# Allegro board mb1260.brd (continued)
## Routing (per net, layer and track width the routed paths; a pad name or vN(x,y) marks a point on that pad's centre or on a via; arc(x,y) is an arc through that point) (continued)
LCD_PSRAM_D12: length 52.1
  TOP w0.127: U10.E2 v2(45.2,32.89) ; U8.R11 37.76,41.46 v2(37.63,41.33)
  L4_SIG w0.102: v2(45.2,32.89) 45.69,32.89 45.82,33.02 45.82,33.43 45.95,33.55 46.18,33.55 46.3,33.43 46.3,32.56 46.18,32.44 45.19,32.44 45.06,32.31 45.06,32.13 45.19,32 45.52,32 45.64,31.88 45.64,31.65 45.52,31.52 44.63,31.52 43.92,30.81 43.92,27.61 44.3,27.23 44.3,24.82 44.17,24.69 43.28,24.69 43.15,24.56 43.15,24.36 43.28,24.23 44.22,24.23 44.35,24.1 44.35,23.9 44.22,23.77 43.28,23.77 43.15,23.65 43.15,18.26 43.79,17.63 44.7,17.63 44.83,17.5 44.83,17.25 44.7,17.12 44.22,17.12 44.09,16.99 44.09,16.76 44.22,16.64 v1(44.42,16.64)
  BOTTOM w0.127: v2(37.63,41.33) 37.63,41.71 37.75,41.83 38.05,41.83 38.18,41.71 38.18,41.12 38.3,41 38.56,41 38.68,41.12 38.68,42.08 38.56,42.2 37.26,42.2 37.13,42.08 37.13,41.15 37.26,41.02 37.26,39.49 37.95,38.81 38.69,38.81 39.32,38.18 40.16,38.18 40.82,37.52 41.69,37.52 42.04,37.17 42.04,36.7 43.31,35.43 43.31,34.29 43.84,33.76 44.04,33.76 44.4,33.4 45.8,33.4 45.95,33.25 45.95,32.38 45.82,32.26 45.57,32.26 45.44,32.38 45.44,32.76 45.31,32.89 v2(45.2,32.89) ; v1(44.42,16.64) 44.42,16.36 43.23,15.16 CN17.6
LCD_PSRAM_D13: length 46.7
  TOP w0.127: v2(41.4,41.68) 41.4,41.73 41.53,41.86 41.87,41.86 42,41.73 42,40.74 42.13,40.61 42.38,40.61 42.48,40.71 42.48,42.06 42.38,42.16 40.91,42.16 40.58,42.49 40.45,42.49 U8.P15 ; U10.F2 44.6,32.49 44.48,32.62 44.48,33.78 44.35,33.91 44.09,33.91 43.97,34.04 43.97,36.53 44.07,36.63 44.37,36.63 44.5,36.5 44.5,35.51 44.63,35.38 v2(45.24,35.38)
  L4_SIG w0.102: v1(42.93,16.74) 42.93,16.97 42.21,17.68 42.21,26.11 42.27,26.16 42.27,29.62 42.39,29.74 42.95,29.74 43.08,29.87 43.08,31.39 44.07,32.38 44.07,33.17 45.67,34.77 45.67,35.18 45.47,35.38 v2(45.24,35.38)
  BOTTOM w0.127: v2(45.24,35.38) 45.29,35.38 45.8,34.87 46.2,34.87 46.96,35.64 46.96,36.51 46.19,37.29 45.16,37.29 45.16,37.29 45.15,37.29 44.89,37.55 44.89,37.56 44.88,37.57 44.88,38.6 43.54,39.94 42.86,39.94 42.09,40.72 42.09,41.12 41.91,41.51 41.73,41.68 v2(41.4,41.68) ; CN17.5 v1(42.93,16.74)
LCD_PSRAM_D14: length 47.8
  TOP w0.127: U8.P14 39.39,42.26 v2(39.39,42.25) ; v2(45.21,34.85) 44.45,34.85 44.35,34.75 44.35,34.54 44.48,34.42 45.34,34.42 45.47,34.29 45.47,34.04 45.34,33.91 44.98,33.91 44.85,33.78 U10.F1
  L4_SIG w0.102: v2(45.21,34.85) 45.09,34.85 43.21,32.97 43.21,32.31 42.57,31.67 42.57,30.61 41.94,29.97 41.94,26.95 41.48,26.49 41.48,18.19 41.58,18.08 41.74,18.08 41.87,17.96 41.87,17.81 41.74,17.68 41.58,17.68 41.48,17.58 41.48,17.35 41.61,17.22 42.11,17.22 42.24,17.09 42.24,16 42.14,15.9 42.14,14.25 v1(42.57,13.82)
  BOTTOM w0.127: v2(45.21,34.85) 45.16,34.8 44.96,34.8 44.83,34.92 44.83,35.94 44.96,36.07 45.9,36.07 46.02,36.2 46.02,36.38 45.88,36.53 44.85,36.53 44.84,36.53 44.83,36.53 44.53,36.83 44.06,36.83 43.56,37.33 43.56,38.84 43.22,39.18 42.25,39.18 42.12,39.04 41.45,39.04 41.33,39.17 41.33,39.84 40.64,40.53 40.64,42.14 40.84,42.34 40.84,42.6 40.84,42.6 40.63,42.81 40.63,43.07 40.51,43.18 39.27,43.18 39.14,43.05 39.14,42.87 39.27,42.75 40.16,42.75 40.31,42.6 40.31,42.29 40.08,42.06 39.57,42.06 39.39,42.24 v2(39.39,42.25) ; CN17.4 42.63,13.87 v1(42.57,13.82)
LCD_PSRAM_D15: length 47.9
  TOP w0.127: v2(45.85,35.66) 45.9,35.71 45.9,36.88 45.77,37.01 45.52,37.01 45.39,36.88 45.39,36.04 45.26,35.92 45.06,35.92 44.93,36.04 44.93,36.98 44.81,37.11 43.71,37.11 43.59,36.98 43.59,33.76 U10.G1 ; v2(41,42.96) 41,42.97 40.94,43.03 40.69,43.03 40.49,43.23 U8.N15
  L4_SIG w0.102: v2(45.85,35.66) 45.75,35.76 45.08,35.76 44.86,35.54 44.86,35.53 44.7,35.38 43.59,34.14 43.17,33.68 42.55,32.62 41.99,31.69 41.68,30.65 41.17,26.67 41.17,16.66 41.38,16.23 v1(41.71,15.9)
  BOTTOM w0.127: v2(45.85,35.66) 45.85,35.46 45.95,35.36 46.15,35.36 46.58,35.79 46.58,36.36 46.03,36.91 45,36.91 45,36.91 44.99,36.91 44.69,37.21 44.22,37.21 43.94,37.49 43.94,38.05 44.07,38.18 44.32,38.18 44.45,38.3 44.45,38.49 44.31,38.63 44.09,38.63 43.94,38.79 43.94,39 43.38,39.56 43.02,39.56 42.58,39.56 42.45,39.69 42.45,39.81 42.16,40.11 41.81,40.11 41.71,40.21 41.71,41.04 41.68,41.1 41.49,41.29 41.19,41.29 41,41.48 41,42.04 41.12,42.16 41.33,42.16 41.44,42.28 41.44,42.49 41.26,42.88 41.17,42.96 v2(41,42.96) ; CN17.3 42.33,16.53 41.71,15.91 v1(41.71,15.9)
LCD_PSRAM_NOE: length 56.7
  TOP w0.127: v2(36.75,48.69) 36.75,48.72 U8.D10 ; U10.A2 48.6,32.55 v2(49.94,33.88)
  L4_SIG w0.102: v1(51.69,18.03) 51.79,18.14 51.79,18.77 51.82,18.8 51.82,18.8 52.07,19.05 52.07,19.05 52.2,19.18 52.2,31.22 49.94,33.48 v2(49.94,33.88) 49.94,33.93 50.06,34.06 51.18,34.06 51.31,34.19 51.31,35.48 50.06,36.73 47.9,36.73 47.42,37.21 46.57,37.21 46.47,37.31 46.47,37.42 46.35,37.54 46.18,37.54 46.06,37.42 46.06,37.31 45.96,37.21 43.93,37.21 43.83,37.31 43.83,37.7 43.71,37.82 43.54,37.82 43.42,37.7 43.42,37.31 43.32,37.21 41.5,37.21 41.39,37.33 41.39,38.7 41.35,38.74 41.35,38.74 40.61,39.49 40.61,40.82 40.03,41.4 38.86,41.4 37.85,42.42 36.77,42.42 36.4,42.79 36.4,48.33 36.75,48.69 v2(36.75,48.69)
  BOTTOM w0.127: v1(51.69,18.03) 51.94,17.78 51.94,16.84 50.83,15.72 48.67,15.72 47.13,17.26 CN17.19
LCD_PSRAM_NWE: length 57.3
  TOP w0.127: v1(52.02,40.39) 52.58,40.39 52.88,40.08 52.88,23.24 51.99,22.35 48.9,22.35 R64.1 44.07,21.36 45.97,19.46 45.97,17.78 46.86,16.89 v1(46.86,16.76) ; v2(37.44,50.06) U8.C11
  L4_SIG w0.102: v1(52.02,40.39) 52.02,40.56 49.43,43.15 47.96,43.15 45.42,45.69 40.41,45.69 39.64,46.47 39.09,46.79 38.07,47.8 38.07,49.05 37.66,49.83 v2(37.44,50.06)
  BOTTOM w0.127: v1(46.86,16.76) 47,16.76 47.37,16.38 47.37,14.68 CN17.20
LCD_RST: length 43
  TOP w0.127: v1(52.25,18.62) 52.12,18.49 51.51,18.49 51.18,18.16 51.18,17.4 ; U8.N12 v2(38.74,42.91)
  L4_SIG w0.102: v1(52.25,18.62) 52.5,18.87 52.5,31.75 51.94,32.31 51.94,35.31 50.19,37.06 48.11,37.06 46.48,38.68 44.75,38.68 42.57,40.86 42.57,41.42 41.85,42.15 41.31,42.15 41.28,42.12 40.31,42.12 39.61,42.82 38.82,42.82 v2(38.74,42.91)
  BOTTOM w0.127: CN17.23 48.33,16.82 49.05,16.1 50.6,16.1 51.22,16.73 51.22,18.2 51.51,18.49 52.12,18.49 v1(52.25,18.62)
LCD_TE_INT: length 64
  TOP w0.127: v2(42.19,46.51) 42.06,46.51 41.69,46.88 41.6,46.88 40.97,47.5 40.53,47.5 40.48,47.45 40.03,47.45 U8.G14
  L4_SIG w0.102: v1(56.52,41.02) 56.77,40.77 56.77,34.67 57.4,34.04 57.4,23.88 58.04,23.24 58.04,15.75 v1(57.4,15.11)
  BOTTOM w0.127: v1(56.52,41.02) 51.51,46.02 48.47,46.02 47.7,46.02 47.62,46.1 42.6,46.1 v2(42.19,46.51) ; v1(57.4,15.11) 52.96,15.11 51.82,13.97 50.9,13.97 49.88,12.95 47.99,12.95 47.57,13.37 42.31,13.37 42.03,13.65 CN17.2
LED_STLINK: length 22.6
  TOP w0.127: v1(47.37,76.52) 47.43,76.59 U2.30 ; v1(38.1,82.04) R14.1 R13.1
  L4_SIG w0.102: v1(38.1,82.04) 38.1,81.92 41.91,78.11 43.56,78.11 44.7,76.96 46.93,76.96 v1(47.37,76.52)
LEDA: length 26.5
  TOP w0.127: L8.2 v1(28.83,11.81)
  L4_SIG w0.102: v1(50.8,14.73) 50.8,13.72 50.04,12.95 48.13,12.95 46.48,11.3 39.22,11.3 38.18,12.34 29.36,12.34 v1(28.83,11.81)
  BOTTOM w0.127: v1(50.8,14.73) 50.7,14.63 CN17.28
LEDK: length 34.4
  TOP w0.127: v1(22.34,22.73) 22.34,22.72 R66.2 21.91,21.65 U12.4
  BOTTOM w0.127: v1(22.34,22.73) 22.35,22.73 23.11,21.97 24.64,21.97 26.54,20.07 35.48,20.07 36.36,19.19 50.53,19.19 50.75,18.97 50.75,18.36 50.13,17.74 CN17.29
MIC_VDD1: length 9.4
  TOP w0.127: 7.49,64.59 7.49,64.81
  TOP w0.229: 13,60.44 U7.A7
  TOP w0.508: 7.49,64.59 TP1.1 8.76,62.36 C29.2 12.4,60.58 12.54,60.44 13,60.44
MIC_VDD2: length 7.9
  TOP w0.127: TP2.1 7.62,59.94 9.78,59.94 C31.2 10.77,59.18 v1(11.48,59.89) ; 14.12,59.94 U7.B6 14.12,59.94 ; 14.12,59.94 v3(13.96,59.78)
  BOTTOM w0.127: v3(13.96,59.78) 13.96,59.63 13.59,59.26 13.31,59.26 12.95,59.61 11.76,59.61 v1(11.48,59.89)
NC1: length 8.2
  TOP w0.127: U8.B5 33.53,50.71 33.53,51.64 33.55,51.66 33.55,52.28 33.17,52.65 32.69,52.65 32.41,52.94 32.41,53.42 32.7,53.71 32.7,55.96 32.64,56.03 32.64,56.64 TP3.1
NC4: length 4.4
  TOP w0.102: 36.78,52.17 36.78,50.7 U8.B9
  TOP w0.127: TP5.1 37.08,53.1 36.78,52.8 36.78,52.17
NC8: length 8.5
  TOP w0.127: U8.D2 31.6,49.4 30.93,49.4 30.81,49.52 30.47,49.52 30.24,49.75 30.24,50.12 29.43,50.93 26.04,50.93 TP14.1
NC10: length 13.6
  TOP w0.127: v1(25.7,53.52) 25.65,53.57 25.65,54.86 26.54,55.75 TP8.1 ; v2(33.55,48.75) 33.53,48.75 U8.E4
  BOTTOM w0.127: v2(33.55,48.75) 33.03,48.75 32.29,49.49 32.29,49.95 31.27,50.98 30.07,50.98 29.14,51.91 27.62,51.91 26.06,53.47 25.76,53.47 v1(25.7,53.52)
NC11: length 9.6
  TOP w0.127: TP13.1 23.75,52.07 24.51,51.31 25.12,51.31 25.88,50.55 29.21,50.55 29.86,49.9 29.86,49.52 30.29,49.08 U8.D1
NETB1_2: length 7.6
  BOTTOM w0.127: B1.2 B1.4 77.84,43.07 77.85,43.05 76.58,43.05
NETB2_1: length 7.9
  BOTTOM w0.127: B2.1 73.82,33.86 SB34.2 73.84,34.8 R91.1 C87.2 77.85,33.05 B2.3
NETC8_2: length 1.7
  TOP w0.508: U3.4 59.88,74.48 C8.2
NETC9_2: length 7.1
  TOP w0.508: 65.91,72.9 65.59,72.9 65.28,72.58 U3.1 ; 65.91,72.9 65.91,71.25 ; 65.91,72.9 65.91,74.17 C9.2 65.6,74.48 U3.3
NETC18_1: length 6.3
  TOP w0.127: U7.B7 v3(13.96,60.6)
  TOP w0.381: v1(12.06,62.1) 12.06,62.84 10.67,64.24 C18.1
  BOTTOM w0.254: v3(13.96,60.6) 13.94,60.58 12.57,60.58 12.06,61.09 v1(12.06,62.1)
NETC18_2: length 28.1
  TOP w0.381: C18.2 10.67,68.16 18.16,75.65 18.16,84.07 19.32,85.23 CN4.4
NETC19_2: length 4.8
  TOP w0.127: C19.2 12.06,63.63 12.95,62.74 14.1,62.74 14.62,62.22 U7.C9
NETC21_1: length 3.2
  TOP w0.127: U7.D9 15.12,64.13 C21.1
NETC24_1: length 5.9
  TOP w0.127: v1(18.16,63.75) 18.16,63.88 C24.1 ; U7.E6 v3(15.78,60.1)
  BOTTOM w0.127: v1(18.16,63.75) 16.33,61.93 16.33,60.65 v3(15.78,60.1)
NETC25_1: length 5
  TOP w0.127: U7.H8 17.25,60.94 18.54,62.23 18.54,62.74 C25.1
NETC25_2: length 6.6
  TOP w0.127: v1(19.66,65.3) 19.66,65.38 C25.2 ; U7.G8 v3(16.78,61.1)
  BOTTOM w0.127: v3(16.78,61.1) 16.87,61.19 16.87,61.77 19.66,64.57 v1(19.66,65.3)
NETC26_1: length 4.7
  TOP w0.127: C26.1 19.68,63.12 v1(19.3,62.74) ; U7.G7 v3(16.78,60.6)
  BOTTOM w0.127: v3(16.78,60.6) 16.87,60.69 17.25,60.69 v1(19.3,62.74)
NETC27_1: length 8
  TOP w0.127: U7.D7 v3(14.96,60.6)
  TOP w0.381: C27.1 10.79,62.97 10.79,62.36 11.86,61.29 12.75,61.29 v1(12.95,61.09)
  BOTTOM w0.254: v3(14.96,60.6) 14.71,60.6 14.1,61.21 13.08,61.21 v1(12.95,61.09)
NETC27_2: length 18.2
  TOP w0.381: CN4.6 11.32,70.68 9.02,68.38 9.02,66.27 C27.2
NETC28_1: length 3.6
  TOP w0.127: C28.1 18.54,61.59 17.38,60.44 U7.H7
NETC30_1: length 29.2
  TOP w0.127: U7.H6 17.65,59.94
  TOP w0.381: 17.65,59.94 17.91,60.2 C30.1 20.07,60.45 20.45,60.83 22.35,60.83 24.89,63.37 24.89,82.91 CN5.6
NETC30_2: length 1.1
  TOP w0.127: C30.2 R31.1
NETC32_1: length 44.9
  TOP w0.127: U7.G6 v3(16.78,60.1)
  TOP w0.381: v1(18.49,59.61) 18.92,59.18 C32.1 20.83,58.42 24,58.42 24.77,59.18 24.77,61.85 25.78,62.87 25.78,77.47 27.81,79.5 27.81,80.7 29.34,82.22 30.76,82.22 33.14,84.6 CN5.4
  BOTTOM w0.381: v1(18.49,59.61) 18.01,60.1 v3(16.78,60.1)
NETC32_2: length 1.1
  TOP w0.127: C32.2 R33.1
NETC43_2: length 3.6
  TOP w0.127: C43.2 16.12,55.59 U7.F1
NETC48_2: length 4.9
  TOP w0.152: R49.1 26.67,48.39 25.4,48.39 C48.2 23.63,49.02 X2.1
NETC51_2: length 4.7
  TOP w0.152: R50.1 26.67,47.88 24.89,47.88 C51.2 24.51,48.26 23.38,48.26 X2.2
NETC67_1: length 8.2
  TOP w0.508: C67.1 L2.2 L3.2 L4.1 24.51,27.05 C69.2
NETC75_2: length 15.9
  TOP w0.381: U12.6 22.56,16.46
  TOP w0.508: C75.2 21.26,13.16 ; C75.2 21.26,11.23 ; C75.2 20.47,12.19 ; C75.2 22.05,12.19 ; 22.35,9.68 C76.2 ; C76.2 21.7,10.29 ; C76.2 22.35,10.9 ; 22.25,13.65 Z1.2 ; Z1.2 22.25,16.32 ; Z1.2 20.9,14.99 ; L8.1 26.42,10.41 25.4,9.4 22.73,9.4
NETC86_2: length 2.8
  BOTTOM w0.127: R90.1 C86.2 73.84,42.04 SB33.2
NETCN7_1: length 14.5
  TOP w0.127: U7.C3 v3(14.46,58.6)
  BOTTOM w0.203: 12.56,58.27 12.62,58.27 12.63,58.25 12.69,58.25 12.85,58.09 13.77,58.09 13.86,58.18 14.19,58.18 14.46,58.45 v3(14.46,58.6)
  BOTTOM w0.508: CN7.1 4.38,59.56 4.01,59.94 4.01,60.59 4.55,61.13 5.75,61.13 7.52,59.36 8.64,59.36 9.73,58.27 12.56,58.27
NETCN7_2: length 14.5
  TOP w0.127: U7.B3 v3(13.96,58.6)
  BOTTOM w0.203: 12.73,58.86 13.17,58.42 13.65,58.42 13.83,58.6 v3(13.96,58.6)
  BOTTOM w0.508: CN7.2 2.77,59.56 3.25,60.05 3.25,60.9 4.23,61.89 6.06,61.89 7.83,60.12 8.95,60.12 10.04,59.03 12.56,59.03 12.73,58.86
NETCN10_1: length 13.3
  TOP w0.203: v3(13.65,56.74) 14.07,57.16 14.07,57.39 U7.B1
  BOTTOM w0.508: v3(13.65,56.74) 13.27,56.74 12.51,55.98 7.59,55.98 6.63,56.95 4.5,56.95 4.06,56.51 4.06,55.85 4.42,55.5 CN10.1
NETCN10_2: length 13.3
  TOP w0.203: U7.A2 13.38,57.94 v3(12.91,57.46)
  BOTTOM w0.508: v3(12.91,57.46) 12.91,57.46 12.19,56.74 7.91,56.74 6.94,57.71 4.19,57.71 3.3,56.82 3.3,55.88 2.92,55.5 CN10.2
NETCN11_8: length 2.4
  TOP w0.508: 61.34,44.83 61.37,44.8 CN11.8
NETCN12_1: length 2.8
  TOP w0.508: R58.1 15.52,40.77 CN12.1
NETCN14_1: length 10.8
  BOTTOM w0.127: R92.2 6.68,24.77 6.15,24.23 5.36,24.23 5.05,23.93 5.05,22.83 5.69,22.2 9.5,22.2 CN14.1
NETCN14_8: length 18.2
  BOTTOM w0.127: CN14.8 3.38,22.68 4.78,21.29 4.78,20.04 5.33,19.48 11.94,19.48 12.27,19.81 12.27,23.9 R97.1
NETCN15_5: length 4.2
  BOTTOM w0.127: CN15.5 15.5,7.73 SB36.2 19.72,7.73
NETCN15_6: length 5
  BOTTOM w0.127: CN15.6 16.38,5.18 17.52,4.04 SB38.2 SB37.2
NETCN16_8: length 8.5
  BOTTOM w0.127: CN16.8 25.7,79.96 26.29,79.38 26.29,77.85 25.42,76.98 25.42,75.79 24.66,75.03 ; 24.66,75.03 SB2.1 ; 24.66,75.03 SB4.1
NETCN17_24: length 4.2
  TOP w0.127: v1(48.53,13.45) 48.11,13.86 SB16.2 SB15.2
  BOTTOM w0.127: CN17.24 48.63,13.55 v1(48.53,13.45)
NETD1_2: length 8.3
  TOP w0.127: D1.2 45.97,91.71 45.97,83.95
NETD2_2: length 39.3
  TOP w0.508: 67.12,71.26 67.84,71.26 68.3,70.79 68.3,42.75 67.3,41.75 D5.2 D4.2 D3.2 D2.2
NETL6_2: length 6.7
  TOP w0.254: U12.8 24.13,17.18 24.13,15.39 Z1.1
  TOP w0.508: L6.2 25.91,17.45 25.15,16.69 25.15,15.6 Z1.1
NETL7_2: length 7.2
  TOP w0.254: v1(25.91,16.26) 26.29,16.26 R69.2 R71.2 26.67,13.46 L7.2 ; v1(23.62,16.51) 23.21,16.92 U12.7
  L4_SIG w0.254: v1(25.91,16.26) 25.65,16.51 v1(23.62,16.51)
NETLD1_1: length 1.8
  BOTTOM w0.127: LD1.1 R12.1
NETLD2_1: length 1.5
  TOP w0.127: LD2.1 41.27,92.58 R1.2
NETLD3_1: length 1.4
  TOP w0.127: LD3.1 R2.1
NETLD3_2: length 18.6
  TOP w0.127: LD3.2 58.93,93.87 v1(58.78,93.87)
  TOP w0.508: U1.8 62.1,80.01 v1(61.47,80.64) R15.1
  BOTTOM w0.127: v1(58.78,93.87) 58.8,93.84 58.8,83.31 v1(61.47,80.64)
NETLD4_2: length 1.8
  TOP w0.127: LD4.2 38.09,89.93 R14.2
NETLD4_3: length 1.8
  TOP w0.127: R13.2 36.59,89.93 LD4.3
NETLD5_1: length 1.5
  BOTTOM w0.127: LD5.1 R47.2
NETLD6_1: length 1.5
  BOTTOM w0.127: LD6.1 R48.2
NETLD7_1: length 1.8
  TOP w0.127: v1(38.76,2.29) R81.2
  BOTTOM w0.127: v1(38.76,2.29) R81.2
NETLD7_2: length 13.1
  TOP w0.127: v1(37.85,4.67) 40.77,7.59 40.77,9.78 R78.1 38.73,10.92 38.03,10.22 U13.3 38.09,9.4 R80.2
  BOTTOM w0.127: LD7.2 v1(37.85,4.67)
NETLD8_1: length 2
  TOP w0.127: R82.1 v1(40.77,2.29)
  BOTTOM w0.127: R82.1 v1(40.77,2.29)
NETLD8_2: length 7.6
  TOP w0.127: T1.3 44.03,8.92 v1(39.75,4.65)
  BOTTOM w0.127: LD8.2 v1(39.75,4.65)
NETLD9_1: length 1.8
  TOP w0.127: v1(58.17,2.29) R83.1
  BOTTOM w0.127: R83.1 v1(58.17,2.29)
NETLD9_2: length 16.4
  TOP w0.127: T2.3 47.96,7.03 48.39,6.6 58.5,6.6 59.05,6.05 v1(59.05,4.67)
  BOTTOM w0.127: LD9.2 v1(59.05,4.67)
NETLD10_1: length 1.8
  TOP w0.127: R84.1 v1(60.07,2.29)
  BOTTOM w0.127: R84.1 v1(60.07,2.29)
NETR3_2: length 1.8
  TOP w0.127: U2.44 44.84,82.92 R3.2
NETR7_1: length 4.3
  TOP w0.127: 51.69,83.95 v1(50.93,83.95) 49.02,83.95
  BOTTOM w0.127: v1(50.93,83.95) 50.67,83.95 49.85,83.12 T3.1
NETR10_1: length 3.2
  TOP w0.155: R10.1 v1(50.87,84.96)
  BOTTOM w0.155: v1(50.87,84.96) 51.75,84.08 T3.2
NETR12_2: length 126.2
  TOP w0.127: v1(61.34,41.66) 61.34,40.77
  L4_SIG w0.102: v1(61.34,41.66) 60.83,42.16 54.81,42.16 51.94,45.03 51.94,70.48 53.34,71.88 53.34,74.04 52.45,74.93 45.47,74.93 43.03,77.37 41.63,77.37 38,81 22.53,81 20.09,78.56 20.09,77.58 22.56,75.12 24.2,75.12 24.89,74.42 24.89,61.09 24,60.2 24,55.63 18.03,49.66 13.97,49.66 v1(10.67,46.35)
  BOTTOM w0.127: R12.2 9.91,47.12 v1(10.67,46.35)
NETR17_2: length 2.7
  TOP w0.127: U2.2 40.37,79.08 40.01,79.45 40.01,79.88 R17.2
NETR19_2: length 2.3
  TOP w0.127: U2.3 40.29,78.59 R19.2
NETR22_1: length 2.1
  TOP w0.381: U1.5 R22.1
NETR35_2: length 4.7
  TOP w0.127: U7.F3 v3(16.28,58.28) ; v1(17.63,58.75) 18.85,57.53 R35.2
  BOTTOM w0.127: v1(17.63,58.75) 16.75,58.75 v3(16.28,58.28)
NETR39_2: length 3.5
  TOP w0.127: R39.2 18.69,55.91 17.19,57.4 17.15,57.4 U7.H1
NETR41_2: length 4.9
  TOP w0.127: R41.2 19.43,55.37 v1(19.18,55.37) ; U7.G2 v3(16.78,57.78)
  L4_SIG w0.102: v3(16.78,57.78) 16.9,57.78 19.18,55.5 v1(19.18,55.37)
NETR46_1: length 6
  TOP w0.127: R46.1 14.27,55.3 v1(15.24,56.26) ; U7.D4 14.96,59.1 v3(14.96,59.28) 15.12,59.44 U7.D5
  BOTTOM w0.127: v3(14.96,59.28) 15.37,58.87 15.37,56.39 v1(15.24,56.26)
NETR55_2: length 1.9
  TOP w0.127: R55.2 23.84,42.33 X3.1
NETR63_1: length 8
  TOP w0.102: 49,29.08 49,29.67 48.77,29.9 48.2,29.9 U10.B5
  TOP w0.127: 49,29.08 49,27.36 49.66,26.7 R63.1 49.77,24.9 R65.2
NETR64_2: length 5.6
  TOP w0.127: U10.G5 44.1,30 43.74,29.64 43.74,25.24 R64.2
NETR67_2: length 1.8
  TOP w0.127: R67.2 23.21,21.87 U12.2
NETR72_2: length 3.9
  TOP w0.127: R73.1 60.96,14.73 59.94,13.72 R72.2 60,13.64 U14.4
NETR74_1: length 2.4
  TOP w0.127: T1.1 41.78,10.64 R74.1 R75.1
NETR76_2: length 2.4
  TOP w0.127: T2.1 45.72,10.64 R76.2 R77.1
NETR85_1: length 2.9
  BOTTOM w0.127: R85.1 19.19,84.45 18.68,84.97 18.68,85.67 19.18,86.17 U16.2
NETR86_1: length 2.9
  BOTTOM w0.127: U17.2 4.34,86.17 3.83,85.67 3.83,84.97 4.34,84.45 R86.1
NETR100_1: length 6.7
  TOP w0.102: 48.68,28.96 48.68,29.41 U10.A6
  TOP w0.127: R100.1 48.12,25.01 48.12,28.28 48.68,28.84 48.68,28.96
NRST: length 138.3
  TOP w0.127: U8.J1 30.91,46.19 29.48,46.19 29.08,45.8 29.08,42.8 R57.1 27.62,41.34 26.31,41.34 25.86,40.89 C93.2 25.27,40.77 v1(24.64,40.13) ; v1(50.01,72.26) 50.42,71.86 50.42,65.26 v1(48.66,63.5) SB10.2 50.13,62.33 R28.2
  L4_SIG w0.102: v1(50.01,72.26) 41.68,72.26 39.27,69.85 33.78,69.85 28.52,64.59 28.52,58.78 26.47,56.72 26.47,53.34 26.8,53.01 26.8,51.31 27.97,50.13 29.12,50.13 29.37,49.88 29.37,49.62 29.77,49.23 29.77,47.78 29.54,47.55 29.54,46.81 27.43,44.7 27.43,42.93 27.28,42.78 27.28,42.19 26.75,41.66 26.24,41.66 25.22,40.64 25.22,40.51 24.84,40.13 v1(24.64,40.13) 24,40.77 22.35,40.77 17.25,35.66 CN12.3 ; v1(70.48,35) 70.48,35.53 70.21,35.81 62.74,35.81 62.29,36.26 62.29,39.43 59.94,41.78 54.48,41.78 49.73,46.53 49.73,58.6 48.66,59.67 v1(48.66,63.5)
  BOTTOM w0.127: v1(70.48,35) 71.25,35.76 SB34.1
OSC_25M: length 1.6
  TOP w0.127: X3.3 26.51,45.3 R51.1
OSC_IN: length 6.8
  TOP w0.203: U2.5 40.02,77.59 C4.2 38.73,77.72 35.82,77.72 X1.2
OSC_OUT: length 6.4
  TOP w0.203: U2.6 39.49,77.08 C6.2 38.73,76.45 35.81,76.45 X1.1
PC14-OSC32_IN: length 3.4
  TOP w0.152: R49.2 28.15,48.43 U8.E1
PC15-OSC32_OUT: length 3.6
  TOP w0.152: R50.2 28.33,48.02 31.03,48.02 U8.F1
PDRON: length 8.3
  TOP w0.102: U8.C6 v2(34.84,50.06)
  TOP w0.127: R37.2 34,56.1 34,55.6 33.87,55.47 33.87,54.52 34.42,53.98 33.76,53.31 v2(33.71,53.31)
  BOTTOM w0.127: v2(33.71,53.31) 33.71,51.49 34.84,50.35 v2(34.84,50.06)
PH0-OSCIN: length 4
  TOP w0.127: R51.2 28.07,45.89 29.17,46.99 29.9,46.99 30.35,47.45 30.95,47.45 U8.G1
PH1-OSCOUT: length 6.6
  TOP w0.127: U8.H1 31.18,46.57 29.32,46.57 28.7,45.95 28.7,43.69 28.19,43.18 TP15.1
PMOD#1: length 96.3
  TOP w0.127: U20.8 40.99,62.45 v1(40.51,61.98)
  L4_SIG w0.102: P2.1 70.07,10.67 71.88,10.67 77.6,16.38 77.6,45.56 76.33,46.83 76.33,49.56 71.12,54.76 71.12,61.85 P1.1
  BOTTOM w0.127: v1(40.51,61.98) 40.51,60.83 41.66,59.69 50.04,59.69 53.21,62.87 71.41,62.87 P1.1
PMOD#2: length 93.9
  TOP w0.127: U20.16 43.78,64.23 44.25,64.69 v1(44.32,64.69)
  L4_SIG w0.102: P2.2 70.07,13.21 72.52,13.21 75.82,16.51 75.82,22.61 76.91,23.7 76.91,45.28 75.64,46.55 75.64,49.17 70.36,54.46 70.36,63.63 71.23,64.5 P1.2
  BOTTOM w0.127: v1(44.32,64.69) 44.96,64.06 44.96,62.23 46.86,60.33 49.15,60.33 52.58,63.75 69.6,63.75 70.34,64.5 P1.2
PMOD#3: length 95.4
  TOP w0.127: U20.5 40.52,64.23 v1(40.28,64.47)
  L4_SIG w0.102: P1.3 69.98,64.71 69.98,54.25 75.31,48.92 75.31,46.41 76.58,45.14 76.58,23.88 75.44,22.73 75.44,17.4 73.53,15.49 69.82,15.49 P2.3
  BOTTOM w0.127: P1.3 66.88,66.5 64.9,64.52 48.64,64.52 46.99,66.17 41.99,66.17 v1(40.28,64.47)
PMOD#4: length 91.6
  TOP w0.127: U20.13 45.37,63.03 v1(48.26,65.91)
  L4_SIG w0.102: P1.4 70.87,67.59 70.87,66.29 69.6,65.02 69.6,54.13 74.93,48.79 74.93,46.25 76.2,44.98 76.2,24.26 74.93,22.99 74.93,19.43 73.66,18.16 69.94,18.16 P2.4
  BOTTOM w0.127: v1(48.26,65.91) 49.28,64.9 64.64,64.9 66.67,66.93 70.2,66.93 P1.4
PMOD_GPIO_0: length 74.7
  TOP w0.127: v2(36.37,52.03) 36.37,52.02 35.99,51.64 35.99,51.33 36.14,51.18 36.14,50.71 U8.B8
  L4_SIG w0.102: v1(57.4,16.13) 57.4,23.11 57.02,23.5 57.02,33.78 56.26,34.54 56.26,37.47 55.12,38.61 55.12,40.23 49.12,46.23 49.12,52.1 v1(46.86,54.36)
  BOTTOM w0.127: P2.9 69.82,12.95 67.18,12.95 65.53,11.3 62.94,11.3 62.15,12.09 62.15,13.72 59.74,16.13 v1(57.4,16.13) ; v2(36.37,52.03) 36.39,52.03 36.45,52.1 37.11,52.1 37.33,52.31 39.23,52.31 40.01,53.09 40.01,53.82 40.31,54.13 46.63,54.13 v1(46.86,54.36)
PMOD_GPIO_1: length 92.6
  TOP w0.127: v2(33.55,48.11) 33.23,47.78 U8.F4
  L4_SIG w0.102: v1(18.29,35.31) 18.29,35.56 21.84,39.12 24.74,39.12 25.78,40.16 26.62,40.16 26.9,40.44 26.92,40.44 27.08,40.59 27.08,41.12 27.89,41.93 27.89,42.52 28.32,42.95 28.32,43.54 29.28,44.5 30.34,44.5 30.76,44.92 30.76,46.2 31.42,46.86 31.42,47.19 31.8,47.57 31.91,47.57 33.02,47.57 v2(33.55,48.11)
  BOTTOM w0.127: v1(18.29,35.31) 18.8,34.8 24.16,34.8 30.96,27.99 30.96,23.87 34.39,20.45 35.71,20.45 36.58,19.57 54.61,19.57 57.04,17.14 59.44,17.14 62.59,14 62.59,12.34 63.25,11.68 65.02,11.68 66.67,13.34 69.47,13.34 70.23,14.1 70.23,15.91 P2.10
PMOD_INT: length 140.6
  TOP w0.127: U8.R13 39.06,41.33 v2(39.34,41.05)
  L4_SIG w0.102: v1(24.41,53.44) 24.41,53.82 25.22,54.64 25.22,58.88 26.59,60.25 v1(26.59,60.99) ; P1.11 73.11,61.84 73.11,53.28 76.71,49.68 76.71,46.99 77.98,45.72 77.98,16.04 P2.7
  BOTTOM w0.127: P1.11 72.23,60.96 58.55,60.96 57.28,59.69 50.67,59.69 50.29,59.31 36.83,59.31 36.68,59.16 35.71,59.16 35.08,59.79 34.09,59.79 33.66,60.22 32,60.22 31.65,60.58 27,60.58 v1(26.59,60.99) ; v1(24.41,53.44) 24.41,52.6 26.07,50.94 27.17,50.94 27.55,50.56 29.39,50.56 30.8,49.15 31.88,49.15 32.77,48.26 32.77,47.75 33.15,47.37 33.66,47.37 34.29,46.74 37.47,46.74 37.82,46.38 37.82,44.63 37.64,44.45 37.64,43.99 37.85,43.79 38.23,43.79 38.35,43.66 38.35,42.75 38.57,42.54 38.93,42.54 39.02,42.44 39.02,41.98 39.42,41.58 39.42,41.12 v2(39.34,41.05)
PMOD_RESET: length 130.2
  TOP w0.127: U8.R6 34.51,41.96 34.19,41.64 34.19,40.12 35.47,38.84 35.47,37.3 36.27,36.5 36.27,21.03 34.25,19.01 v1(34.25,18.8)
  L4_SIG w0.102: P2.8 72.41,11.95 77.22,16.76 77.22,45.4 75.95,46.67 75.95,49.43 70.74,54.64 70.74,63.25 70.99,63.5 72.77,63.5 P1.12
  BOTTOM w0.127: P2.8 70.2,10.8 67.94,10.8 66.42,9.27 62.87,9.27 61.01,11.13 61.01,12.01 58.8,14.22 53.34,14.22 52.32,13.21 51.21,13.21 50.2,12.19 45.69,12.19 45.44,11.94 42.64,11.94 38.27,16.31 36.74,16.31 v1(34.25,18.8)
PMOD_SEL_0: length 20.5
  TOP w0.127: v1(39.62,58.55) 39.62,63.43 39.75,63.56 39.75,65.53 40.26,66.04 R102.1 41.25,65.43 41.56,65.43 42.09,64.9 U20.3 ; U8.D13 v2(39.39,49.41)
  L4_SIG w0.102: v1(39.62,58.55) 40.13,58.04 40.13,55.5 39.5,54.86 39.5,51.5 39.39,51.4 v2(39.39,49.41)
PMOD_SEL_1: length 27
  TOP w0.102: U8.E3 32.56,48.43 32.23,48.1 32.22,48.1 32.22,48.11 v2(32.24,48.11)
  TOP w0.127: U20.10 42.09,62.41 42.04,62.36 R29.2 v1(41.38,61.21)
  L4_SIG w0.102: v1(41.38,61.21) 41.4,61.21 41.27,61.09 40.39,61.09 39.75,61.72 36.32,61.72 35.81,61.21 35.81,60.96 35.29,60.44 34.07,60.44 33.2,59.56 31.62,59.56 29.87,57.81 29.87,55.27 29.97,55.17 29.97,51.49 31.95,49.5 31.95,48.39 v2(32.24,48.11)
PMOD_SPI2_MISO: length 15.5
  TOP w0.127: v2(40.04,50.06) 40.03,50.05 40.03,50.05 U8.C14 ; U20.6 40.59,63.83 40.57,63.81 40.54,63.81 40.01,63.28 40.01,58.8 v1(40.26,58.55)
  L4_SIG w0.102: v1(40.26,58.55) 40.51,58.29 40.51,55.37 39.8,54.66 39.8,51.77 40.04,51.53 v2(40.04,50.06)
PMOD_SPI2_MOSI: length 21.9
  TOP w0.127: v1(45.97,65.28) 43.64,65.28 U20.1 ; U8.C13 39.4,50.06 39.4,51.31 39.75,51.66 39.75,52.19 39.88,52.32 39.88,52.32 40.09,52.53 v2(40.24,52.53)
  L4_SIG w0.102: v2(40.24,52.53) 40.39,52.68 40.39,54.23 45.59,59.44 45.59,64.9 v1(45.97,65.28)
PMOD_SPI2_NSS: length 31.9
  TOP w0.127: v1(50.55,52.7) 47.85,52.7 43.31,57.25 43.31,58.42 40.89,60.83 40.89,61.47 41.27,61.85 41.27,62.1 41.69,62.52 U20.9 ; U8.E14 40.05,48.1 41.52,48.1 41.99,47.62 50.04,47.62 v1(50.55,48.13)
  L4_SIG w0.102: v1(50.55,48.13) v1(50.55,52.7)
PMOD_SPI2_SCK: length 21.4
  TOP w0.127: v1(46.05,64.52) 45.72,64.52 44.63,63.43 U20.14 ; v2(40.04,49.41) U8.D14
  L4_SIG w0.102: v2(40.04,49.41) 40.39,49.76 40.39,50.22 42.55,52.37 42.55,54.36 45.34,57.15 45.34,58.67 46.61,59.94 46.61,63.96 v1(46.05,64.52)
PMOD_UART7_CTS: length 31.8
  TOP w0.127: U8.L2 31.58,44.86 30.9,44.86 30.74,45.02 30.2,45.02 30.19,45.01 v2(30.17,45.01) ; U20.7 40.69,63.43 40.49,63.22 40.49,62.64 v1(40.48,62.62)
  L4_SIG w0.102: v1(40.48,62.62) 38.37,62.62 37.85,62.1 35.31,62.1 33.15,59.94 31.5,59.94 27.88,56.32 27.88,55.21 28.37,54.71 28.37,52.17 28.6,51.94 29.08,51.94 30.76,50.27 30.78,50.27 31.11,49.93 31.11,47.83 30.45,47.17 30.45,46.69 30.53,46.61 30.53,45.37 v2(30.17,45.01)
PMOD_UART7_RTS: length 34.7
  TOP w0.102: v2(32.89,44.86) 32.89,44.86 U8.L3
  TOP w0.127: U20.12 42.89,62.52 43.62,61.79 43.62,60.64 v1(43.81,60.45)
  L4_SIG w0.102: v2(32.89,44.86) 33.23,45.19 33.91,45.19 34.01,45.29 34.01,46.45 34.11,46.55 34.11,47.11 34.01,47.21 34.01,48.46 34.62,49.07 34.62,49.48 34.08,50.02 34.08,50.17 33.63,50.62 31.78,50.62 30.58,51.82 30.58,55.48 30.51,55.55 30.51,57.43 32.03,58.95 33.69,58.95 33.91,59.17 36.69,59.17 37.59,60.07 41.66,60.07 42.55,60.96 43.31,60.96 v1(43.81,60.45)
PMOD_UART7_RXD: length 32.7
  TOP w0.127: v1(40.31,65.18) 40.51,64.97 41.25,64.97 U20.4 ; U8.K2 31.58,45.51 31.13,45.51 30.85,45.8 v2(30.18,45.8)
  L4_SIG w0.102: v1(40.31,65.18) 37.62,62.48 35.18,62.48 32.97,60.27 31.22,60.27 27.41,56.46 27.41,55.17 28.04,54.53 28.04,51.36 28.55,50.85 29.31,50.85 29.98,50.18 29.98,49.88 30.45,49.4 30.45,47.6 30.15,47.29 30.15,45.82 v2(30.18,45.8)
PMOD_UART7_TXD: length 37.5
  TOP w0.127: v2(29.63,45.78) 30.01,45.4 30.77,45.4 30.99,45.18 U8.K1 ; U20.15 44.12,63.83 44.3,64.01 v1(44.32,64.01)
  L4_SIG w0.102: v1(44.32,64.01) 44.3,64.01 42.65,65.66 40.13,65.66 37.34,62.87 35.05,62.87 32.77,60.58 30.91,60.58 26.82,56.49 26.82,53.64 27.23,53.24 27.23,51.56 28.35,50.44 29.29,50.44 29.68,50.05 29.68,49.75 30.07,49.35 30.07,47.65 29.84,47.42 29.84,46 29.79,45.95 29.79,45.95 v2(29.63,45.78)
PSRAM_A0: length 60.7
  TOP w0.127: U10.A3 49.08,31.74 50.94,29.88 v2(51.09,29.49) ; v2(31.59,48.11) U8.E2 ; 48.64,17.65 49.09,18.1 49.09,18.22 49.99,19.13 51.18,19.13 v1(51.33,18.97)
  L4_SIG w0.102: v1(51.33,18.97) 51.89,19.53 51.89,28.78 51.18,29.49 v2(51.09,29.49)
  BOTTOM w0.127: v2(51.09,29.49) 51.09,28.41 51.19,28.31 51.19,27.22 48.9,24.92 41.07,24.92 38.84,25.51 30.65,33.7 30.65,41.25 30.66,41.27 31.11,42.37 31.11,45.01 31.98,45.87 31.98,46.26 31.88,46.58 v2(31.59,48.11)
PSRAM_A1: length 43.9
  TOP w0.102: v2(32.24,45.51) 32.24,46.15 U8.H3
  TOP w0.127: v2(50.8,28.14) 50.8,28.65 50.19,29.26 50.19,29.54 48.74,30.99 U10.A4
  BOTTOM w0.127: v2(32.24,45.51) 32.02,45.51 31.34,44.83 31.34,42.04 31.03,41.27 31.03,33.86 38.95,25.95 41.13,25.3 43.94,25.3 44.07,25.43 44.07,25.78 44.2,25.91 44.41,25.91 44.54,25.78 44.54,25.43 44.67,25.3 45.92,25.3 46.05,25.43 46.05,25.81 46.17,25.93 46.43,25.93 46.55,25.81 46.55,25.43 46.68,25.3 46.91,25.3 47.04,25.43 47.04,25.82 47.16,25.95 49.09,25.95 50.8,27.66 v2(50.8,28.14)
PSRAM_A2: length 46.2
  TOP w0.127: U8.H2 31.58,46.81 30.99,46.81 v2(30.84,46.96) ; U10.A5 48.8,30.24 49.28,29.77 49.28,29.1 49.94,28.44 49.94,27.66 50.98,26.62 v2(50.98,25.88)
  BOTTOM w0.127: v2(50.98,25.88) 49.25,24.16 39.12,24.16 29.89,33.38 29.89,41.58 30.48,42.64 30.57,42.79 30.57,46.7 v2(30.84,46.96)
PSRAM_A3: length 46.3
  TOP w0.102: v2(31.59,46.16) 31.91,45.84 U8.J2
  TOP w0.127: v2(51.49,28.58) 51.43,28.58 50.57,29.44 50.57,29.7 48.93,31.34 48.25,31.34 U10.B3
  BOTTOM w0.102: 30.89,45.45 v2(31.59,46.16)
  BOTTOM w0.127: v2(51.49,28.58) 51.64,28.43 51.64,27.1 49.07,24.54 39.28,24.54 30.27,33.54 30.27,41.43 30.48,41.82 30.89,42.57 30.89,45.45
PSRAM_A4: length 41.5
  TOP w0.102: U10.B4 48.24,30.61 48.74,30.61 49.49,29.86 49.49,29.7 49.53,29.66 ; U8.J3 32.84,45.55 32.84,45.55 v2(32.89,45.51)
  TOP w0.127: 49.53,29.66 49.81,29.38 49.81,29.1 50.37,28.54 v2(50.37,27.81)
  BOTTOM w0.127: v2(32.89,45.51) 32.89,45.46 32.54,45.11 32.08,45.11 31.6,44.63 31.6,41.83 31.42,41.27 31.42,34.01 39.15,26.28 41.18,25.68 42.42,25.68 42.55,25.81 42.55,26.11 42.67,26.24 42.93,26.24 43.05,26.11 43.05,25.81 43.18,25.68 43.56,25.68 43.69,25.81 43.69,26.2 43.81,26.33 48.88,26.33 v2(50.37,27.81)
PSRAM_A5: length 41.5
  TOP w0.102: v2(32.24,44.21) 32.24,44.89 32.53,45.18 U8.K3
  TOP w0.127: v2(46.71,31.34) 46.71,31.36 U10.C3
  BOTTOM w0.127: v2(32.24,44.21) 32.24,44.04 32.37,43.92 33.13,43.92 33.25,44.04 33.25,44.34 33.16,44.43 32.58,44.43 32.28,44.73 32.08,44.73 31.83,44.48 31.83,42.62 31.95,42.49 32.36,42.49 32.49,42.37 32.49,42.19 32.36,42.06 32,42.06 31.88,41.94 31.88,41.58 32,41.45 32.13,41.45 32.26,41.33 32.26,39.78 32.59,39.45 32.59,37.78 32.46,37.66 31.93,37.66 31.8,37.53 31.8,36.26 31.93,36.13 32.46,36.13 32.59,36.01 32.59,35.19 32.46,35.06 31.92,35.06 31.8,34.95 31.8,34.17 39.35,26.62 40.73,26.21 41.25,26.21 41.53,26.49 41.53,27.03 41.66,27.15 42.03,27.15 42.72,27.85 46.09,27.85 46.23,27.99 46.23,30.12 46.35,30.25 46.94,30.25 47.07,30.38 47.07,31.22 46.94,31.34 v2(46.71,31.34)
PSRAM_A6: length 41.6
  TOP w0.127: U10.C4 47.03,30.99 v2(46.66,30.63) ; U8.P6 34.51,42.58 v2(34.19,42.26)
  BOTTOM w0.127: v2(34.19,42.26) 34.19,42.12 34.01,41.94 33.45,41.94 33.35,41.83 33.35,41.66 33.22,41.53 33.05,41.53 32.92,41.4 32.92,41.07 33.05,40.94 33.22,40.94 33.35,40.82 33.35,40.57 33.22,40.45 33.12,40.45 33.02,40.35 33.02,40.09 33.17,39.94 33.22,39.94 33.35,39.81 33.35,34.87 33.57,34.66 33.57,34.51 33.16,34.1 33.16,33.89 33.34,33.71 33.52,33.71 33.7,33.9 33.93,34.12 34.11,34.12 34.72,33.51 34.72,33.33 34.34,32.95 34.34,32.77 34.52,32.59 34.7,32.59 35.08,32.97 35.26,32.97 35.44,32.79 35.44,32.61 35.06,32.23 35.06,32.05 35.24,31.87 35.42,31.87 35.8,32.25 35.98,32.25 36.15,32.07 36.15,31.89 35.78,31.51 35.78,31.33 35.96,31.15 36.14,31.15 36.51,31.53 36.69,31.53 36.85,31.37 36.85,31.19 36.45,30.79 36.45,30.6 38.14,28.91 38.53,28.91 38.66,28.78 38.66,28.42 38.79,28.3 39.01,28.3 39.14,28.42 39.14,28.83 39.52,29.21 39.52,29.77 39.65,29.9 39.88,29.9 40.01,29.77 40.01,29.46 40.13,29.34 41.3,29.34 41.43,29.21 41.43,28.19 41.55,28.07 41.86,28.07 41.99,28.19 41.99,29.44 42.11,29.57 42.75,29.57 42.88,29.44 42.88,29.21 42.75,29.08 42.44,29.08 42.32,28.96 42.32,28.74 42.44,28.61 42.72,28.61 45.35,28.61 45.47,28.73 45.47,29.34 45.72,29.59 45.72,30.12 45.59,30.25 45.29,30.25 45.16,30.38 45.16,30.68 45.29,30.81 45.64,30.81 45.81,30.97 46.56,30.97 46.66,30.87 v2(46.66,30.63)
PSRAM_A7: length 41.6
  TOP w0.127: U10.D4 46.35,30.93 v2(46.03,30.6) ; U8.N6 34.51,43.23 v2(34.19,42.91)
  BOTTOM w0.127: v2(34.19,42.91) 34.19,43.05 34.06,43.18 33.4,43.18 33.27,43.05 33.27,42.8 33.4,42.67 33.71,42.67 33.82,42.56 33.82,42.37 33.7,42.24 33.4,42.24 33.17,42.01 33.17,42.01 33.05,41.89 32.56,41.89 32.44,41.76 32.44,41.55 32.64,41.35 32.64,39.94 32.97,39.6 32.97,37.31 32.84,37.19 32.28,37.19 32.18,37.08 32.18,36.7 32.28,36.6 32.84,36.6 32.97,36.47 32.97,34.77 32.84,34.65 32.36,34.65 32.23,34.52 32.23,34.28 38.62,27.89 38.94,27.89 39.07,27.76 39.07,27.44 39.2,27.3 39.4,27.3 39.52,27.43 39.52,28.65 39.65,28.78 39.9,28.78 40.03,28.65 40.03,26.92 40.18,26.77 40.44,26.7 41.05,26.7 41.15,26.8 41.15,27.15 41.05,27.25 40.61,27.25 40.49,27.38 40.49,28.8 40.61,28.93 40.87,28.93 41,28.8 41,27.66 41.12,27.53 41.87,27.53 42.57,28.23 45.78,28.23 45.85,28.3 45.85,29.11 45.98,29.25 45.98,30.56 v2(46.03,30.6)
PSRAM_A8: length 41.5
  TOP w0.127: v2(34.83,41.57) 34.57,41.31 34.57,40.28 34.72,40.13 34.92,40.13 35.05,40.26 35.05,40.92 35.24,41.12 35.24,41.8 35.26,41.82 35.26,41.86 35.18,41.93 U8.R7 ; v2(40.72,32.38) 40.79,32.46 42.37,32.46 42.49,32.59 42.49,32.84 42.37,32.97 41.99,32.97 41.86,33.1 41.86,33.43 41.99,33.55 42.49,33.55 42.77,33.83 42.77,34.23 42.65,34.35 42.16,34.35 42.04,34.48 42.04,34.74 42.16,34.86 42.52,34.86 42.65,34.99 42.65,35.24 42.52,35.37 42.16,35.37 42.04,35.5 42.04,35.75 42.16,35.88 42.52,35.88 42.65,36.01 42.65,36.63 42.77,36.75 43.08,36.75 43.21,36.63 43.21,33.63 42.84,33.27 42.84,32.31 42.97,32.18 43.22,32.18 43.35,32.31 U10.H2
  BOTTOM w0.127: v2(34.83,41.57) 34.83,41.57 34.82,41.57 34.37,41.57 34.11,41.31 34.11,35.24 37.88,31.47 38.2,31.47 38.33,31.34 38.33,31.09 38.46,30.96 38.71,30.96 38.84,31.09 38.84,31.34 38.96,31.47 39.19,31.47 40.79,31.47 40.92,31.6 40.92,31.83 40.79,31.95 37.9,31.95 37.77,32.08 37.77,32.31 37.9,32.44 40.67,32.44 v2(40.72,32.38)
PSRAM_A9: length 41.8
  TOP w0.127: U8.P7 34.84,42.26 v2(34.84,42.25) ; v2(40.42,29.73) 40.42,24.51 40.3,24.38 39.9,24.38 39.78,24.51 39.78,30.15 39.9,30.28 40.61,30.28 40.74,30.4 40.74,30.73 40.61,30.86 39.9,30.86 39.78,30.99 39.78,31.35 39.9,31.48 40.74,31.48 41.35,32.08 42.59,32.08 42.93,31.74 U10.H3
  BOTTOM w0.127: v2(40.42,29.73) 40.44,29.72 41.25,29.72 41.38,29.84 41.38,30.15 41.25,30.28 39.47,30.28 39.12,29.92 39.12,29.36 38.99,29.24 38.76,29.24 38.63,29.36 38.63,29.82 38.51,29.95 38.35,29.95 38.09,29.68 37.91,29.68 37.76,29.83 37.76,30.01 38.19,30.44 38.19,30.62 38.05,30.76 37.87,30.76 37.44,30.33 37.26,30.33 37.08,30.52 37.08,30.69 37.48,31.1 37.48,31.28 33.73,35.03 33.73,41.25 34.74,42.25 v2(34.84,42.25)
PSRAM_A10: length 41.4
  TOP w0.102: U8.N7 35.16,43.23 v2(34.84,42.91)
  TOP w0.127: v2(42.14,30.76) 41.94,30.76 41.86,30.68 41.86,28.8 41.99,28.68 42.44,28.68 42.57,28.55 42.57,28.22 42.44,28.09 41.99,28.09 41.86,27.97 41.86,27.69 41.99,27.56 42.44,27.56 42.57,27.43 42.57,27.14 42.44,27.01 42.15,27.01 41.99,26.85 41.74,26.85 41.5,27.08 41.5,31.16 41.66,31.32 42.34,31.32 42.67,30.99 U10.H4
  BOTTOM w0.127: v2(42.14,30.76) 42.22,30.84 42.39,30.84 42.51,30.72 42.51,30.55 42.32,30.35 42.32,30.07 42.19,29.95 41.94,29.95 41.81,30.07 41.81,30.53 41.68,30.66 39.34,30.66 39.22,30.78 39.22,30.96 39.34,31.09 41.63,31.09 41.71,31.17 42.04,31.17 42.16,31.29 42.16,31.55 42.04,31.67 41.43,31.67 41.3,31.8 41.3,32.36 40.84,32.82 37.74,32.82 37.54,32.61 37.27,32.61 34.49,35.39 34.49,41.05 34.59,41.15 34.95,41.15 35.33,41.53 35.33,41.99 35.46,42.11 35.99,42.11 36.12,42.24 36.12,42.39 35.99,42.52 35.09,42.52 34.84,42.77 v2(34.84,42.91)
PSRAM_A11: length 41.5
  TOP w0.102: U8.M7 v2(34.84,43.56)
  TOP w0.127: v2(42.72,30.14) 42.74,30.15 43.25,30.15 U10.H5
  BOTTOM w0.127: v2(42.72,30.14) 42.93,30.34 42.93,31.37 42.24,32.05 41.81,32.05 41.68,32.18 41.68,32.7 41.18,33.2 37.23,33.2 37.06,33.37 37.06,33.53 37.19,33.66 39.85,33.66 39.98,33.78 39.98,34.01 39.85,34.14 38.91,34.14 38.79,34.26 38.79,34.37 38.48,34.67 37.9,34.67 37.64,34.92 36.68,34.92 35.5,36.11 35.32,36.11 35.18,35.97 35.18,35.79 36.5,34.47 37.62,34.47 37.74,34.34 37.74,34.11 37.62,33.99 36.44,33.99 34.87,35.55 34.87,40.58 35.64,41.34 35.64,41.71 35.76,41.83 36.27,41.83 36.4,41.96 36.4,46.18 36.27,46.3 36.02,46.3 35.89,46.18 35.89,44.12 35.76,43.99 34.96,43.99 34.84,43.87 v2(34.84,43.56)
PSRAM_A12: length 45.1
  TOP w0.127: U8.L15 40.4,44.5 41.15,44.5 41.63,44.02 43.41,44.02 v1(44.32,43.1) ; v2(41.88,26.31) 41.73,26.31 41.12,26.92 41.12,31.32 41.5,31.7 42.49,31.7 42.8,31.39 43.54,31.39 43.89,31.74 U10.G3
  BOTTOM w0.127: v2(41.88,26.31) 42.13,26.56 42.13,26.72 42.88,27.47 48.33,27.47 48.83,27.97 48.85,27.97 49.94,29.06 49.94,30.03 53.3,33.4 53.3,39.76 50.72,42.34 45.08,42.34 v1(44.32,43.1)
PSRAM_A13: length 42.8
  TOP w0.127: U10.G4 44.1,30.74 43.72,30.36 43.72,30.08 43.48,29.84 43.08,29.84 42.95,29.71 42.95,29.29 43.36,28.88 43.36,26.78 v2(43.27,26.69) ; U8.K15 40.56,45.18 40.72,45.03 41.46,45.03 41.67,44.82 43.96,44.82 v1(45.59,43.18)
  BOTTOM w0.127: v1(45.59,43.18) 45.67,43.1 51.08,43.1 54.91,39.27 54.91,33.93 50.7,29.72 50.7,28.74 48.67,26.71 43.28,26.71 v2(43.27,26.69)
PSRAM_A14: length 44.6
  TOP w0.102: 43,30.65 43.61,30.65 43.74,30.78 43.74,31.17 43.94,31.37 44.47,31.37 U10.F3
  TOP w0.127: v1(44.96,43.13) 43.65,44.44 41.62,44.44 41.3,44.75 40.61,44.75 40.51,44.86 40.04,44.86 U8.K14 ; v2(42.73,26.68) 42.73,26.72 42.95,26.93 42.95,28.75 42.34,29.36 42.34,30.41 42.59,30.65 43,30.65
  BOTTOM w0.127: v1(44.96,43.13) 44.96,43.05 45.29,42.72 50.88,42.72 53.68,39.92 53.68,39.92 53.75,39.85 53.75,33.3 50.32,29.88 50.32,28.9 48.51,27.09 43.04,27.09 42.73,26.78 v2(42.73,26.68)
PSRAM_A15: length 45.2
  TOP w0.102: U10.F4 45.21,31.36 45.21,31.9 45.44,32.13 45.8,32.13 45.95,32.29 45.95,33.48 46.27,33.79
  TOP w0.127: v1(50.98,36.96) 47.29,36.96 47.09,36.75 47.09,35.41 46.27,34.58 46.27,33.79 ; U8.K13 39.38,45.5 40.62,45.5 40.86,45.26 v1(42.8,45.26)
  BOTTOM w0.127: v1(50.98,36.96) 50.95,36.96 50.83,37.08 50.83,39.55 50.7,39.67 50.42,39.67 50.29,39.55 50.29,36.63 50.16,36.5 49.81,36.5 49.68,36.63 49.68,41 49.56,41.12 49.23,41.12 49.1,41 49.1,38.35 48.97,38.23 48.74,38.23 48.62,38.35 48.62,40.36 48.49,40.49 47.6,40.49 47.47,40.36 47.47,39.34 47.34,39.22 47.09,39.22 46.96,39.34 46.96,40.64 46.84,40.77 46.58,40.77 46.46,40.64 46.46,40.34 46.33,40.21 46.08,40.21 45.95,40.34 45.95,40.82 46.2,41.07 46.2,41.71 46.08,41.83 44.93,41.83 43.87,42.9 43.87,44.7 43.31,45.26 v1(42.8,45.26)
PSRAM_A16: length 41.5
  TOP w0.127: v1(46.71,41.27) 46.06,40.63 42.99,40.63 42.86,40.75 42.86,42.49 42.74,42.62 41.58,42.62 41.5,42.54 41.24,42.54 41.12,42.42 40.97,42.42 40.68,42.71 40.68,42.71 40.5,42.9 40.25,42.9 39.91,43.23 U8.N14 ; U10.E4 v2(45.97,31.37)
  BOTTOM w0.127: v1(46.71,41.27) 46.71,41.83 46.84,41.96 50.57,41.96 50.72,41.8 50.72,40.64 50.85,40.51 51.26,40.51 51.82,39.96 51.82,37.39 51.94,37.27 52.78,37.27 52.91,37.14 52.91,36.88 52.78,36.76 51.94,36.76 51.82,36.63 51.82,36.35 51.94,36.22 52.79,36.22 52.92,36.09 52.92,33.59 49.56,30.23 49.56,29.23 48.18,27.85 46.74,27.85 46.61,27.98 46.61,29.74 46.74,29.87 47,29.87 47.13,30 47.13,30 47.35,30.22 47.35,31.6 47.22,31.72 46.33,31.72 v2(45.97,31.37)
PSRAM_A17: length 43.2
  TOP w0.102: 49.53,32.13 46.74,32.13 U10.D3
  TOP w0.127: U8.N13 39.19,43.23 39.51,42.91 39.83,42.91 40.03,42.71 40.03,42.47 40.23,42.26 40.48,42.26 41.01,41.74 41.01,41.52 41.24,41.29 41.49,41.29 41.62,41.16 41.62,40.36 41.74,40.23 46.41,40.23 v1(47.4,41.22) ; 49.53,32.13 51.56,32.13 51.69,32.26 51.69,32.79 51.56,32.92 v2(49.91,32.92)
  BOTTOM w0.127: v2(49.91,32.92) 49.91,32.13 50.04,32 50.39,32 50.52,32.13 50.52,33.02 50.65,33.15 51.89,33.15 52.02,33.27 52.02,33.62 51.89,33.74 50.75,33.74 50.62,33.87 50.62,34.12 50.75,34.25 52.15,34.25 52.27,34.38 52.27,34.63 52.15,34.76 50.75,34.76 50.62,34.89 50.62,35.14 50.75,35.27 52.3,35.27 52.43,35.39 52.43,35.65 52.3,35.78 50.75,35.78 50.62,35.9 50.62,36.16 50.75,36.28 51.31,36.28 51.44,36.41 51.44,39.67 51.05,40.06 50.46,40.06 50.34,40.17 50.34,41.48 50.24,41.58 47.5,41.58 47.4,41.48 v1(47.4,41.22)
PSRAM_NBL0: length 53.2
  TOP w0.127: v2(49.89,34.49) 48.64,33.24 U10.A1 ; v2(32.9,52.25) 33.17,51.99 33.17,51.08 U8.A4
  L4_SIG w0.102: v2(49.89,34.49) 50.88,34.49 51,34.62 51,35.31 49.91,36.4 48.59,36.4 48.46,36.27 48.46,35.59 48.34,35.46 48.03,35.46 47.9,35.59 47.9,36.3 47.29,36.91 41.38,36.91 41.08,37.2 41.08,38.58 41.05,38.62 41.05,38.62 40.3,39.36 40.3,40.67 40.09,40.88 39.68,40.88 39.49,40.69 39.2,40.69 38.99,40.9 38.99,40.99 37.89,42.09 36.65,42.09 36.14,42.6 36.14,48.44 36.35,48.64 36.35,50.52 37.08,51.26 37.08,54.08 36.96,54.2 36.09,54.2 35.97,54.08 35.97,52.38 35.84,52.25 35.1,52.25 34.98,52.38 34.98,54.58 34.85,54.71 34.65,54.71 34.52,54.58 34.52,52.38 34.39,52.25 34.21,52.25 34.09,52.38 34.09,54.48 33.96,54.61 33.38,54.61 33.25,54.48 33.25,52.38 33.12,52.25 v2(32.9,52.25)
PSRAM_NBL1: length 53.1
  TOP w0.127: v2(32.39,51.69) 32.39,51.69 32.56,51.51 U8.A3 ; v2(49.86,35.05) 48.25,33.44 48.25,32.89 U10.B2
  L4_SIG w0.102: v2(49.86,35.05) 47.73,35.05 47.6,35.18 47.6,36.17 47.17,36.6 43.71,36.6 43.59,36.47 43.59,35.22 43.47,35.1 43.3,35.1 43.18,35.22 43.18,36.48 43.06,36.6 42.89,36.6 42.77,36.48 42.77,34.26 42.65,34.14 42.49,34.14 42.37,34.26 42.37,36.47 42.24,36.6 42.09,36.6 41.96,36.47 41.96,34.26 41.84,34.14 41.67,34.14 41.55,34.26 41.55,36.47 41.43,36.6 41.27,36.6 41.15,36.47 41.15,34.26 41.03,34.14 40.86,34.14 40.74,34.26 40.74,38.49 39.98,39.25 39.98,40.07 39.89,40.17 39.77,40.17 39.45,40.49 38.97,40.49 37.67,41.78 36.58,41.78 35.89,42.47 35.89,48.54 36.14,48.79 36.14,50.88 35.61,51.41 35.61,51.82 35.48,51.94 33.4,51.94 33.15,51.69 32.39,51.69 v2(32.39,51.69)
PSRAM_NE1: length 44.8
  TOP w0.127: v1(52.44,39.8) 52.48,39.76 52.48,23.65 52.18,23.36 R65.1 ; U8.A11 37.76,51.51 v2(37.81,51.56)
  L4_SIG w0.102: v1(52.44,39.8) 52.49,39.85 52.49,40.65 49.66,43.48 48.13,43.48 45.58,46.04 44.93,46.04 44.83,46.14 44.83,46.71 44.72,46.81 44.52,46.81 44.42,46.71 44.42,46.14 44.32,46.04 44.11,46.04 44.01,46.14 44.01,46.71 43.91,46.81 43.71,46.81 43.61,46.71 43.61,46.14 43.5,46.04 40.64,46.04 39.22,47.09 38.34,47.97 38.34,52.55 38.22,52.68 37.94,52.68 37.81,52.55 v2(37.81,51.56)
PWR_ENN: length 9
  TOP w0.254: 56.26,77.6 55.5,77.6 54.1,76.2 51.44,76.2 50.82,75.59 U2.28
  TOP w0.508: 56.26,77.6 56.39,77.47 U1.3
PWR_EXT: length 4.1
  TOP w0.254: U2.39 47.34,82.27 R6.2
  TOP w0.508: R4.1 R5.1 R6.2
QSPI_CLK: length 58.7
  TOP w0.127: U6.6 31.5,70.43 31.93,70.87 v1(31.93,71.27) ; U5.6 37.72,70.82 v1(37.64,70.89) ; v2(34.19,44.21) 34.19,44.21 U8.M6
  L4_SIG w0.102: v2(34.19,44.21) 34.42,44.44 34.42,46.24 34.57,46.39 34.57,47.22 34.42,47.38 34.42,48.21 34.77,48.56 35.63,48.56 35.92,48.85 35.92,50.5 35.23,51.18 32.39,51.18 32.03,51.54 32.03,51.84 32.38,52.2 32.38,53.47 32.74,53.82 32.74,56.49 33.53,57.28 37.08,57.28 39.12,59.31 43.94,59.31 45.21,60.58 45.21,67.16 43.88,68.49 43.88,69.66 v1(44.32,70.1)
  BOTTOM w0.127: v1(31.93,71.27) 33.38,71.27 34.32,70.33 37.08,70.33 v1(37.64,70.89) 38,71.25 43.44,71.25 44.32,70.36 v1(44.32,70.1)
QSPI_D0: length 42.5
  TOP w0.127: U8.F14 39.71,47.78 v2(39.39,48.11) ; v1(32.77,70.66) U6.5 ; 38.99,69.81 38.99,70.54 v1(38.86,70.66)
  L4_SIG w0.102: v2(39.39,48.11) 39.39,48.15 40.72,49.49 40.72,50.1 41.2,50.57 45.21,50.57 45.72,51.08 45.72,58.55 46.94,59.77 46.94,66.09 v1(45.34,67.69)
  BOTTOM w0.127: v1(32.77,70.66) 33.12,70.66 33.96,69.82 38.02,69.82 v1(38.86,70.66) 42.37,70.66 v1(45.34,67.69)
QSPI_D1: length 22.1
  TOP w0.127: U8.B14 39.71,50.58 40.05,50.92 40.05,51.16 40.64,51.76 40.64,52.7 40.35,52.99 40.35,56.05 37.97,58.42 37.97,59.56 36.45,61.09 v1(36.45,61.16) 36.45,62.01 ; v1(30.22,61.13) 30.23,61.14 U6.2
  BOTTOM w0.127: v1(36.45,61.16) 36.45,61.09 35.94,60.58 34.92,60.58 33.45,62.05 31.17,62.05 30.24,61.13 v1(30.22,61.13)
QSPI_D2: length 20.5
  TOP w0.127: v1(37.59,61.09) 37.72,61.21 U5.3 ; U8.A2 31.88,51.07 31.88,51.25 31.53,51.59 31.53,52.5 31.25,52.78 31.04,52.78 30.35,53.47 30.35,59.44 31.5,60.58 v1(31.5,61.09) U6.3
  BOTTOM w0.127: v1(37.59,61.09) 36.7,60.2 34.7,60.2 33.23,61.67 32.08,61.67 v1(31.5,61.09)
QSPI_D3: length 68
  TOP w0.127: 36.45,69.81 36.45,70.36 36.96,70.87 v1(36.96,70.94) ; v1(50.55,46.48) 50.55,45.21 48.64,43.31 46.91,43.31 46.22,42.61 44.18,42.61 43.23,43.56 40.82,43.56 40.5,43.88 U8.M15 ; v1(31.19,71.4) 31.19,71.07 30.23,70.1 U6.7
  L4_SIG w0.102: v1(36.96,70.94) 37.64,71.63 38.73,71.63 41.38,74.27 51.98,74.27 52.58,73.68 52.58,72.11 51.33,70.87 51.33,47.27 v1(50.55,46.48)
  BOTTOM w0.127: v1(36.96,70.94) 34.39,70.94 33.58,71.75 31.55,71.75 v1(31.19,71.4)
QSPI_NCS: length 20.4
  TOP w0.127: U6.1 v1(28.96,61.13) ; U8.B6 34.2,50.7 34.2,51.55 34.31,51.66 34.31,52.16 34.79,52.64 34.79,53.5 35.09,53.81 35.09,55.96 35.18,56.05 v1(35.18,61.17) U5.1
  BOTTOM w0.127: v1(35.18,61.17) 34.96,61.17 33.58,62.56 30.38,62.56 v1(28.96,61.13)
REXT_OTGPHY: length 7
  TOP w0.127: R54.1 45.85,44.7 45.49,44.7 45.34,44.86 45.21,45.31 45.21,45.47 44.97,45.71 41.31,45.71 41.24,45.64 40.86,45.64 40.76,45.75 40.45,45.75 U8.J15
SAI2_FS_A: length 27.2
  TOP w0.127: TP11.1 15.62,52.45 v1(16.38,51.69) 16.76,51.31 19.81,51.31 21.46,52.96 25.34,52.96 25.64,52.65 25.64,52.32 25.96,52.01 29.08,52.01 29.44,51.65 29.44,51.46 30.48,50.42 30.73,50.42 31.09,50.06 31.58,50.06 U8.C2 ; U7.E3 v3(15.78,58.28)
  L4_SIG w0.102: v1(16.38,51.69) 17.14,52.45 17.14,55.63 15.47,57.3 15.47,57.97 v3(15.78,58.28)
SAI2_I2C1_SCL: length 18.9
  TOP w0.127: U8.A5 33.86,51.59 33.93,51.66 33.93,52.44 33.33,53.04 32.99,53.04 v2(32.84,53.19) 32.84,53.31 33.08,53.55 33.08,53.78 33.27,53.98 ; v1(21.35,56.79) 21.35,56.77 21.01,56.43 R39.1
  BOTTOM w0.127: v2(32.84,53.19) 32.84,53.34 32.31,53.87 32.31,54.14 31.56,54.89 31.56,55.88 31.19,56.25 30.82,56.25 29.92,57.15 21.71,57.15 v1(21.35,56.79)
SAI2_I2C1_SDA: length 18.8
  TOP w0.127: 30.99,53.98 30.99,53.4 v2(31.11,53.28) 31.23,53.16 31.41,53.16 31.82,52.76 32.05,52.76 32.33,52.47 32.33,52.26 32.88,51.72 32.88,50.71 U8.B4 ; R35.1 21.84,57.53 22.33,57.05 22.33,56.37 22.02,56.06 v1(21.97,56.06)
  BOTTOM w0.127: v2(31.11,53.28) 31.09,53.3 31.09,54.28 29.81,55.56 29.81,56.14 29.55,56.39 22.53,56.39 22.2,56.06 v1(21.97,56.06)
SAI2_INT: length 30
  TOP w0.102: U8.B7 35.47,50.69 35.47,51.16 35.41,51.22 35.41,52.1 35.84,52.53 35.84,52.58
  TOP w0.127: U7.G3 v3(16.78,58.28) ; v1(36.22,58.7) 36.26,58.66 36.26,53.36 35.84,52.94 35.84,52.58
  BOTTOM w0.127: v1(36.22,58.7) 35.59,58.7 34.95,59.33 34.01,59.33 33.5,59.84 31.54,59.84 31.19,60.2 19.94,60.2 17.93,58.19 16.87,58.19 v3(16.78,58.28)
SAI2_MCLK_A: length 29.8
  TOP w0.127: TP6.1 16.46,53.51 v1(16.46,52.86) ; U7.D3 v3(14.96,58.28) ; v2(32.89,49.41) 33.09,49.21 33.09,49.21 U8.D4
  L4_SIG w0.102: v1(16.46,52.86) 16.84,53.23 16.84,55.5 15.19,57.15 15.19,58.04 v3(14.96,58.28)
  BOTTOM w0.127: v1(16.46,52.86) 20.38,52.86 21.75,54.23 21.99,54.23 23.01,55.24 27.3,55.24 28.6,53.95 29.8,53.95 29.95,53.81 29.95,52.8 30.37,52.38 30.37,52.02 30.82,51.56 31.29,51.56 31.41,51.43 32.52,50.33 32.52,49.78 v2(32.89,49.41)
SAI2_SCK_A: length 23.3
  TOP w0.127: v1(19.3,53.59) 19.18,53.59 18.8,53.98 TP7.1 18.8,54.58 16.62,56.76 U7.G1 ; U8.C4 v2(32.89,50.06)
  BOTTOM w0.127: v1(19.3,53.59) 19.64,53.59 21.28,55.23 22.46,55.23 22.85,55.63 27.46,55.63 28.14,54.95 29.34,54.95 30.33,53.96 30.33,52.95 30.75,52.53 30.75,52.17 30.98,51.94 31.45,51.94 32.89,50.5 v2(32.89,50.06)
SAI2_SD_A: length 29.2
  TOP w0.127: v1(18.16,53.59) 18.16,53.21 TP12.1 ; U8.C3 32.23,50.06 32.23,50.51 32.03,50.71 31.78,50.71 31.58,50.92 31.58,51.22 31.13,51.68 31.13,52.32 v2(31.14,52.34) ; U7.E4 v3(15.78,58.78)
  L4_SIG w0.102: v3(15.78,58.78) 16.79,58.78 19.68,55.88 19.68,55.12 v1(18.16,53.59)
  BOTTOM w0.127: v2(31.14,52.34) 31.14,52.68 30.71,53.11 30.71,54.12 29.5,55.33 28.29,55.33 27.62,56.01 22.69,56.01 22.3,55.61 21.12,55.61 19.55,54.04 18.86,54.04 18.41,53.59 v1(18.16,53.59)
SAI2_SD_B: length 31.9
  TOP w0.102: U8.B10 37.46,50.72 37.46,51.82
  TOP w0.127: v1(37.13,58.55) 37.21,58.47 TP4.1 37.21,55.63 38.02,54.81 38.02,52.97 37.77,52.71 37.77,52.13 37.46,51.82 ; U7.F2 v3(16.28,57.78)
  BOTTOM w0.127: v1(37.13,58.55) 36.84,58.25 35.42,58.25 34.75,58.93 33.87,58.93 33.34,59.46 31.38,59.46 31.03,59.82 20.1,59.82 17.66,57.38 16.67,57.38 v3(16.28,57.78)
STLINK_RX: length 2.6
  TOP w0.127: SB9.2 43.08,70.86 42.84,71.1 U2.13
STLINK_TX: length 4.1
  TOP w0.127: U2.12 41.31,74.02 SB8.2
STM_JTCK: length 29.4
  TOP w0.127: U2.37 48.34,81.62 48.77,82.04 v1(49.27,82.04)
  L4_SIG w0.102: v1(49.27,82.04) 49.28,82.04 50.39,80.92 51.28,80.92 51.64,81.28 52.2,81.28 60.96,90.04 60.96,93.98 62.33,95.35 67,95.35 CN2.2
STM_JTMS: length 22.3
  TOP w0.127: v1(52.58,80.64) 52.58,79.88 51.28,78.59 U2.34
  L4_SIG w0.102: CN2.4 62.31,94.39 61.39,93.47 61.39,89.84 52.58,81.03 v1(52.58,80.64)
STM_RST: length 4.7
  TOP w0.127: SB6.2 38.11,74.68 R24.1 C7.2 40.14,76.59 U2.7
STMOD+_ADC_DAC: length 4.2
  BOTTOM w0.127: SB28.1 72.79,65.52 P1.13
STMOD+_I2C2_SCL: length 2.1
  BOTTOM w0.127: P1.7 71.69,74.58 SB25.2
STMOD+_I2C2_SDA: length 1.7
  BOTTOM w0.127: 70.1,80.39 71.66,80.39 P1.10
STMOD+_SPI2_MISOS: length 79.9
  TOP w0.127: v2(33.66,44.31) 33.66,44.31 33.23,43.88 U8.M4
  L4_SIG w0.102: v1(51.44,73.15) 51.44,72.39 50.55,71.5 44.58,71.5 43.56,70.48 43.56,68.33 44.83,67.06 44.83,60.71 43.81,59.69 38.99,59.69 36.96,57.66 32.64,57.66 31.52,56.54 31.52,51.54 32.13,50.93 33.7,50.93 34.28,50.34 34.28,50.11 34.82,49.57 34.82,48.9 34.21,48.29 34.21,47.29 34.34,47.16 34.34,46.45 34.21,46.32 34.21,44.88 33.66,44.33 v2(33.66,44.31)
  BOTTOM w0.127: v1(51.44,73.15) 51.44,75.31 53.34,77.22 63.88,77.22 68.33,81.66 72.26,81.66 72.77,81.15 72.77,79.5 P1.9
STMOD+_SPI2_MOSIS: length 113.7
  TOP w0.127: v2(33.54,43.56) 33.54,43.56 U8.M5
  L4_SIG w0.102: v2(33.54,43.56) 33.54,41.6 34.85,40.28 34.85,36.07 36.2,34.72 36.2,24.77 35.81,24.38 v1(35.81,23.75)
  BOTTOM w0.127: v1(35.81,23.75) 36.45,23.75 37.58,22.62 55,22.62 55.5,23.11 61.41,23.11 63.44,25.15 64.39,25.15 66.55,27.3 66.55,45.47 77.03,55.94 77.03,75.37 74.8,77.6 72.87,77.6 P1.8
STMOD+_TIM2_CH1: length 61.4
  TOP w0.127: v2(39.08,51.86) 39.07,51.86 39.17,51.76 39.17,51.16 39.06,51.06 U8.A13
  L4_SIG w0.102: v1(74.41,57.8) 75.73,59.12 75.73,76.54 P1.19
  BOTTOM w0.127: v2(39.08,51.86) 39.06,51.86 39.47,51.45 40.3,51.45 40.61,51.14 59.63,51.14 62.02,53.53 70.17,53.53 74.41,57.78 v1(74.41,57.8)
STMOD+_TIM3_CH3: length 4.3
  BOTTOM w0.127: P1.14 72.71,69.56 SB29.1
STMOD+_UART4_RXD: length 80.9
  TOP w0.102: U8.E13 39.39,48.76 40.89,48.76 v2(41.02,48.9)
  BOTTOM w0.127: P1.18 76.64,73.63 76.64,56.2 66.04,45.59 66.04,36.32 65.53,35.81 62.87,35.81 62.36,36.32 62.36,39.5 61.59,40.26 60.71,40.26 59.18,41.78 57.78,41.78 50.16,49.4 42.42,49.4 41.78,48.77 41.15,48.77 v2(41.02,48.9)
STMOD+_UART4_RXD_S: length 64.8
  TOP w0.127: U8.B13 38.73,50.71 38.73,51.35 v2(38.77,51.39)
  L4_SIG w0.102: P1.20 76.07,78.2 76.07,58.73 v1(74.05,56.71)
  BOTTOM w0.127: v1(74.05,56.71) 74.05,56.66 70.48,53.09 62.2,53.09 59.88,50.76 40.46,50.76 40.1,51.13 39.04,51.13 v2(38.77,51.39)
